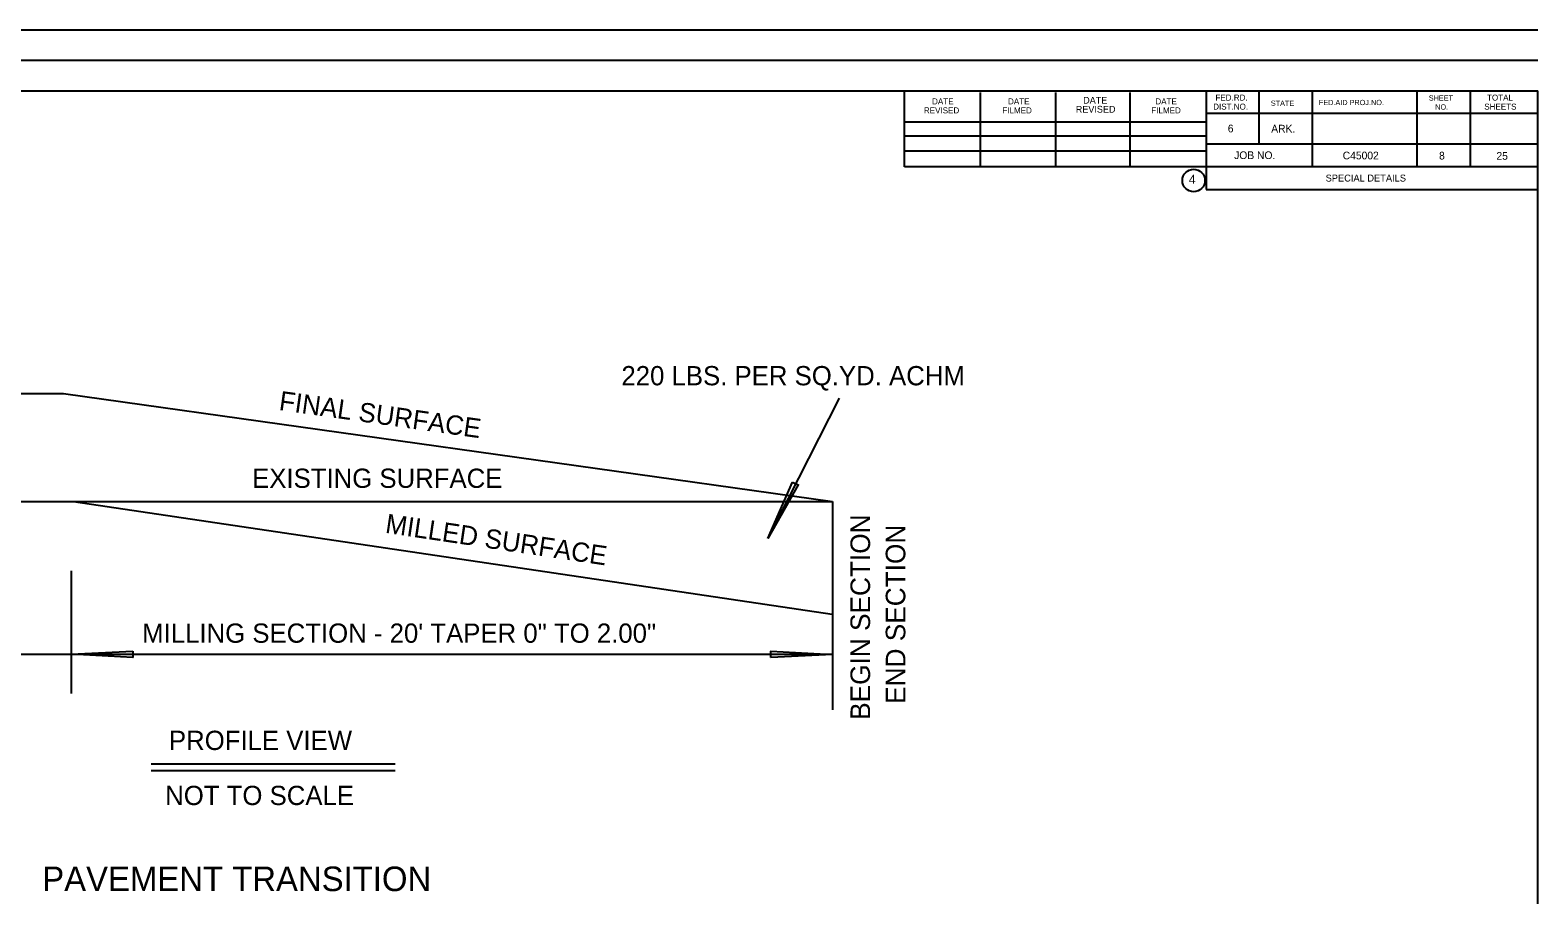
# Model space of a CAD drawing. Extents: x 1944905 to 1956777, y 763871 to 764977.
# Drawn here: x 1952380 to 1953359, y 764415 to 764977 of the extents above; entities that cross this region are included whole.
import ezdxf

# ---------------------------------------------------------------- set-up
doc = ezdxf.new("R2010")
doc.units = 0
for name, color, linetype in [('Default', 7, 'Continuous'), ('R_Border', 7, 'Continuous'), ('R_Dimension', 7, 'Continuous')]:
    doc.layers.add(name, color=color, linetype=linetype)

# ---------------------------------------------------------------- blocks, each defined once
blk = doc.blocks.new('AHD')
at = {"layer": 'R_Dimension'}
for p, q in [((0, 0), (0.796, 1.837)), ((0.975, 1.749), (0, 0)), ((0.796, 1.837), (0.975, 1.749)), ((0.978, 1.754), (0.975, 1.749))]:
    blk.add_line(p, q, dxfattribs=at)

msp = doc.modelspace()

# ---------------------------------------------------------------- linework, layer by layer
at = {"layer": 'Default'}
for p, q in [((1953358.8, 764976.71), (1951740.13, 764976.71)), ((1953358.8, 764957.02), (1951740.13, 764957.02)), ((1951777.89, 764937.29), (1953358.8, 764937.29)), ((1952947.48, 764887.95), (1952947.48, 764937.29)), ((1953143.37, 764937.29), (1953143.37, 764873.29)), ((1953177.57, 764937.29), (1953177.57, 764902.6)), ((1953212.25, 764937.29), (1953212.25, 764887.95)), ((1953280.15, 764937.29), (1953280.15, 764887.95)), ((1953314.83, 764937.29), (1953314.83, 764887.95)), ((1953358.8, 763910.07), (1953358.8, 764937.29)), ((1952996.82, 764887.95), (1952996.82, 764936.31)), ((1953045.67, 764887.95), (1953045.67, 764936.31)), ((1953094.03, 764887.95), (1953094.03, 764936.31)), ((1952947.48, 764917.26), (1953143.37, 764917.26)), ((1953358.8, 764922.63), (1953143.37, 764922.63)), ((1952947.48, 764907.98), (1953143.37, 764907.98)), ((1952947.48, 764898.21), (1953143.37, 764898.21)), ((1953358.8, 764902.6), (1953143.37, 764902.6)), ((1953358.8, 764887.95), (1952947.48, 764887.95)), ((1953143.37, 764873.29), (1953358.8, 764873.29))]:
    msp.add_line(p, q, dxfattribs=at)
msp.add_circle((1953135.26, 764879.01), 7.33, dxfattribs=at)
at = {"layer": 'R_Dimension'}
for p, q in [((1952207.06, 764740.97), (1952401.17, 764740.68)), ((1952401.17, 764740.68), (1952900.73, 764670.5)), ((1952905.02, 764737.63), (1952858.61, 764646.46)), ((1952204.34, 764670.5), (1952407.73, 764670.5)), ((1952407.73, 764670.5), (1952900.57, 764597.41)), ((1952407.73, 764670.5), (1952900.73, 764670.5)), ((1952900.73, 764670.5), (1952900.73, 764535.1)), ((1952406.27, 764625.55), (1952406.27, 764545.87)), ((1952160.03, 764571.28), (1952900.73, 764571.28)), ((1952458.2, 764500.01), (1952616.71, 764500.01)), ((1952458.18, 764495.7), (1952616.75, 764495.7))]:
    msp.add_line(p, q, dxfattribs=at)

# ---------------------------------------------------------------- block references
at = {"layer": 'R_Border', "xscale": 20.32394048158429, "yscale": 19.95381106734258}
msp.add_blockref('AHD', (1952858.61, 764646.46), dxfattribs=at)
at = {"layer": 'R_Border', "xscale": 20.323922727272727, "yscale": 19.953793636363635}
for p, rotation in [((1952406.27, 764571.28), -63.29422944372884), ((1952900.65, 764571.14), 116.51057307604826)]:
    msp.add_blockref('AHD', p, dxfattribs=dict(at, rotation=rotation))

# ---------------------------------------------------------------- texts
at = {"layer": 'Default'}
for s, height, p in [('DATE', 3.91, (1952965.37, 764928.49)), ('DATE', 3.91, (1953014.71, 764928.49)), ('REVISED', 4.396, (1953058.69, 764923.12)), ('DATE', 4.396, (1953063.51, 764928.98)), ('DATE', 3.91, (1953110.41, 764928.49)), ('DIST.NO.', 3.91, (1953147.95, 764925.08)), ('FED.RD.', 3.91, (1953149.41, 764930.94)), ('STATE', 3.42, (1953185.36, 764927.52)), ('FED.AID PROJ.NO.', 3.4203, (1953216.59, 764928.01)), ('SHEET', 3.42, (1953287.97, 764930.94)), ('NO.', 3.42, (1953292.15, 764925.08)), ('SHEETS', 3.91, (1953324.01, 764925.08)), ('TOTAL', 3.91, (1953325.8, 764930.94)), ('REVISED', 3.91, (1952960.07, 764922.63)), ('FILMED', 3.91, (1953011.02, 764922.63)), ('FILMED', 3.91, (1953107.74, 764922.63)), ('6', 5, (1953157.44, 764910.32)), ('ARK.', 5, (1953185.64, 764910.21)), ('JOB NO.', 5, (1953161.56, 764892.97)), ('C45002', 5, (1953232.07, 764892.78)), ('8', 5, (1953294.65, 764892.68)), ('25', 5, (1953331.91, 764892.51)), ('4', 5.86, (1953132.16, 764876.89)), ('SPECIAL DETAILS', 4.5, (1953220.98, 764878.37))]:
    msp.add_text(s, height=height, dxfattribs=at).set_placement(p)
at = {"layer": 'R_Dimension'}
for s, height, p in [('220 LBS. PER SQ.YD. ACHM', 12.5044, (1952763.62, 764746)), ('EXISTING SURFACE', 12.5044, (1952523.74, 764679.38)), ('MILLING SECTION - 20\' TAPER 0" TO 2.00"', 12.5044, (1952452.35, 764578.76)), ('PROFILE VIEW', 12.5044, (1952469.74, 764509.11)), ('NOT TO SCALE', 12.5044, (1952467.3, 764473.33)), ('PAVEMENT TRANSITION', 15.963, (1952387.46, 764417.43))]:
    msp.add_text(s, height=height, dxfattribs=at).set_placement(p)
for s, height, rotation, p in [('FINAL SURFACE', 12.5091, 352.00338, (1952540.75, 764730)), ('MILLED SURFACE', 12.5096, 351.56391, (1952609.77, 764650.24)), ('BEGIN SECTION', 12.7363, 90, (1952925.11, 764528.68)), ('END SECTION', 12.7363, 90, (1952948.01, 764539.06))]:
    msp.add_text(s, height=height, rotation=rotation, dxfattribs=at).set_placement(p)

doc.saveas('drawing.dxf')
